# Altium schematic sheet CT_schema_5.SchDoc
size 368 x 245 mm
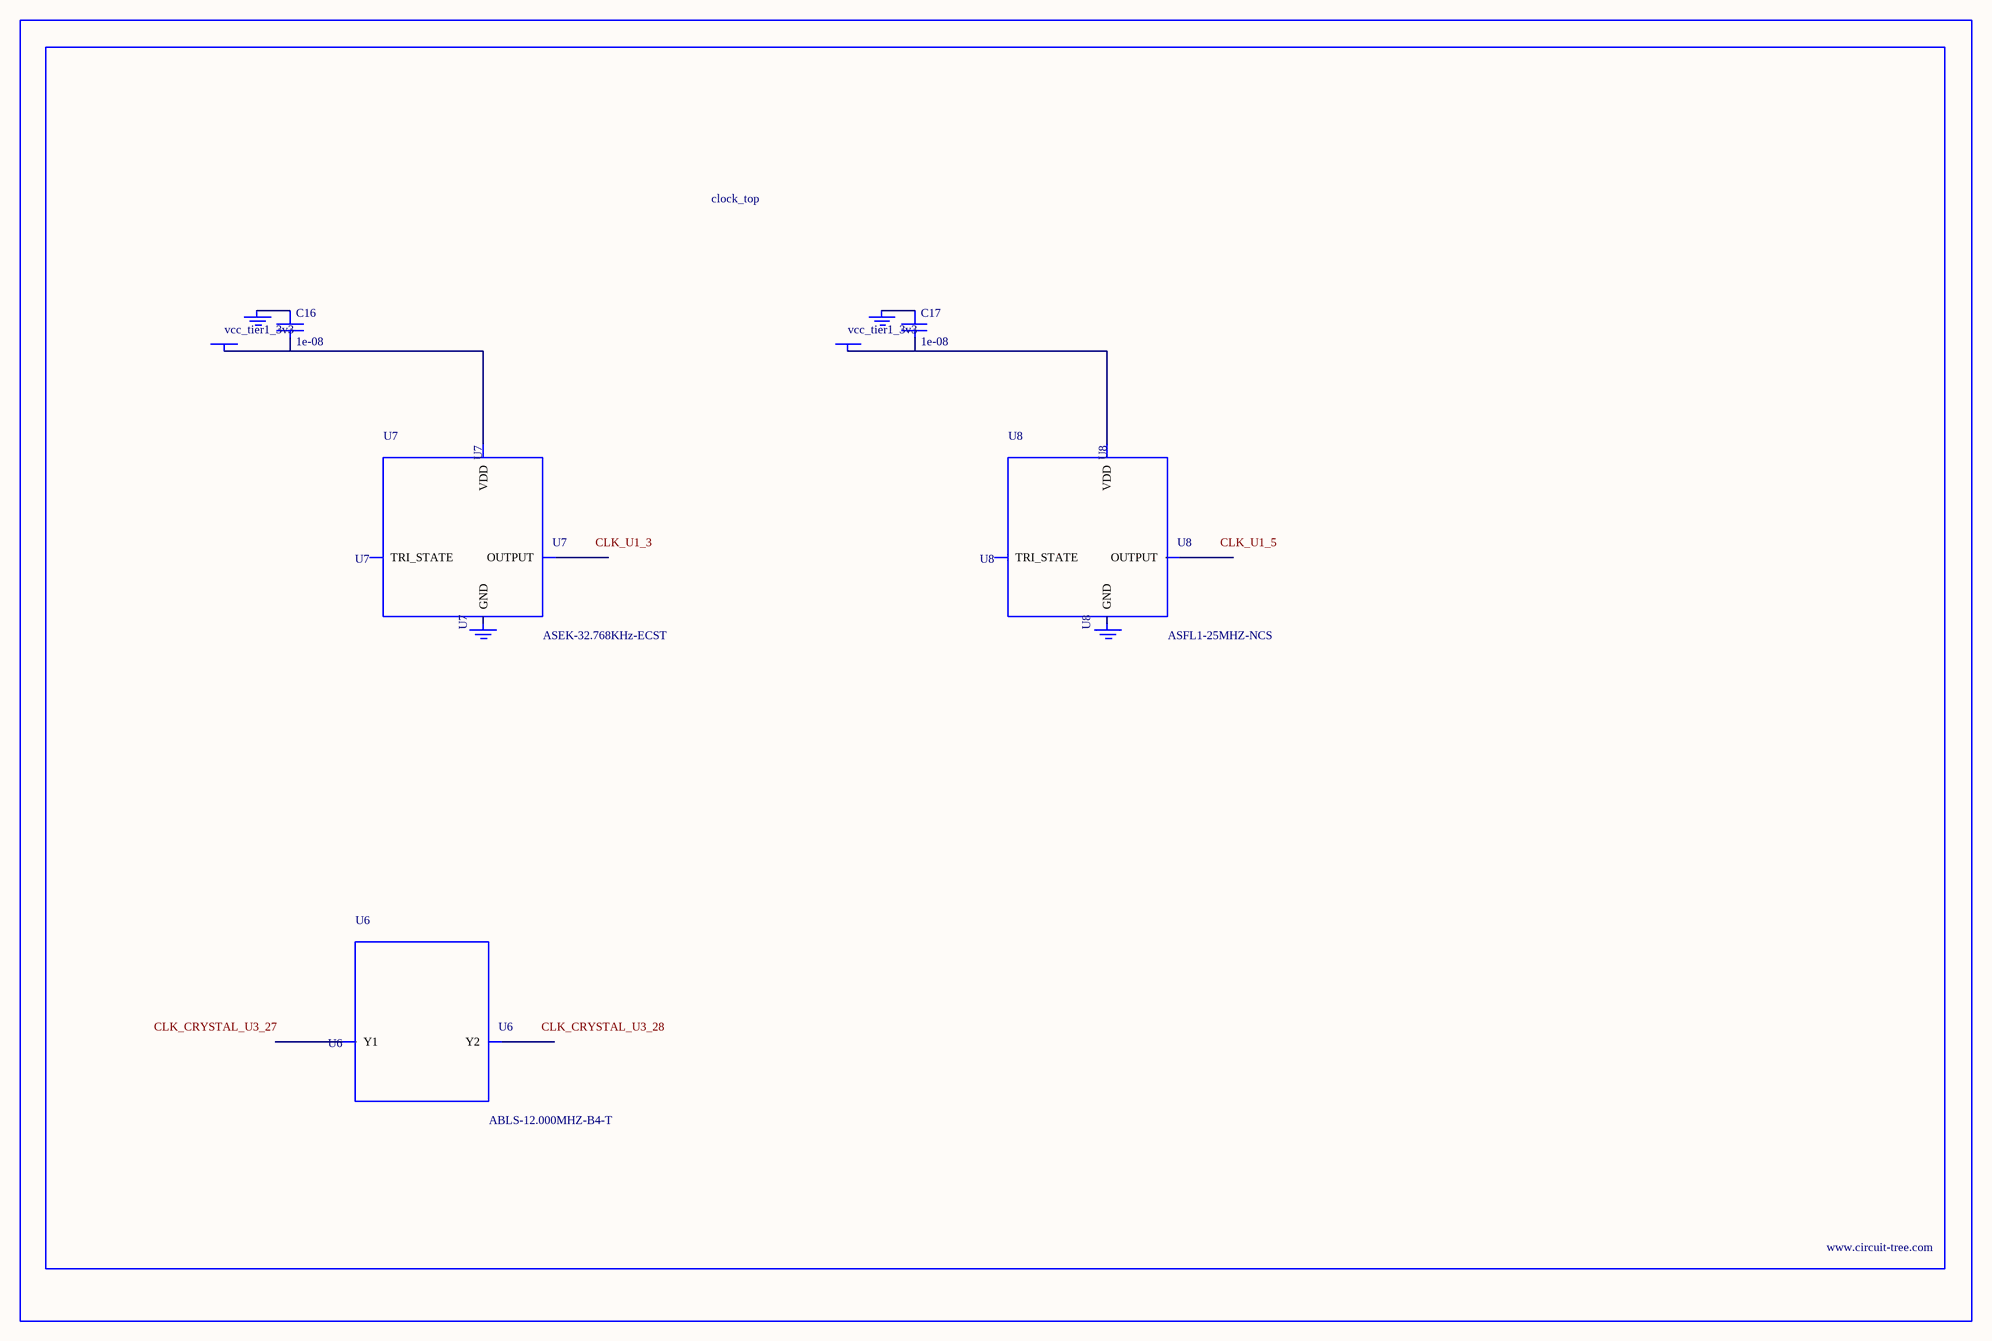
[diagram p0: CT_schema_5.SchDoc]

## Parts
BORDER4  (no value)
C16  1e-08  [C0402]
C17  1e-08  [C0402]
GND_INSTANCE_4_0  (no value)
GND_INSTANCE_4_1  (no value)
GND_INSTANCE_4_2  (no value)
GND_INSTANCE_4_3  (no value)
POWER_INSTANCE_4_0  vcc_tier1_3v3
POWER_INSTANCE_4_1  vcc_tier1_3v3
U6  ABLS-12.000MHZ-B4-T  [ABLS-12.000MHZ-B4-T]
U7  ASEK-32.768KHz-ECST  [ASEK]
U8  ASFL1-25MHZ-NCS  [ASFL1]

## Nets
NetC16_1: C16.1 GND_INSTANCE_4_0.0(GND)
NetC16_2: C16.2 POWER_INSTANCE_4_0.0(PWR) U7.4(VDD)
NetC17_1: C17.1 GND_INSTANCE_4_2.0(GND)
NetC17_2: C17.2 POWER_INSTANCE_4_1.0(PWR) U8.4(VDD)

Not connected (* = marked no-connect by the designer): GND_INSTANCE_4_1 0(GND); GND_INSTANCE_4_3 0(GND); U6 1(Y1) 2(Y2); U7 1(TRI_STATE) 2(GND) 3(OUTPUT); U8 1(TRI_STATE) 2(GND) 3(OUTPUT)

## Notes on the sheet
- Labels drawn without touching a wire or pin: CLK_CRYSTAL_U3_27, CLK_CRYSTAL_U3_28, CLK_U1_3, CLK_U1_5

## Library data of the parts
BORDER4 = BORDER_PAGE4
C16 C17 = C0402C103K3RAC
GND_INSTANCE_4_0-GND_INSTANCE_4_3 = GND
POWER_INSTANCE_4_0 POWER_INSTANCE_4_1 = PWR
